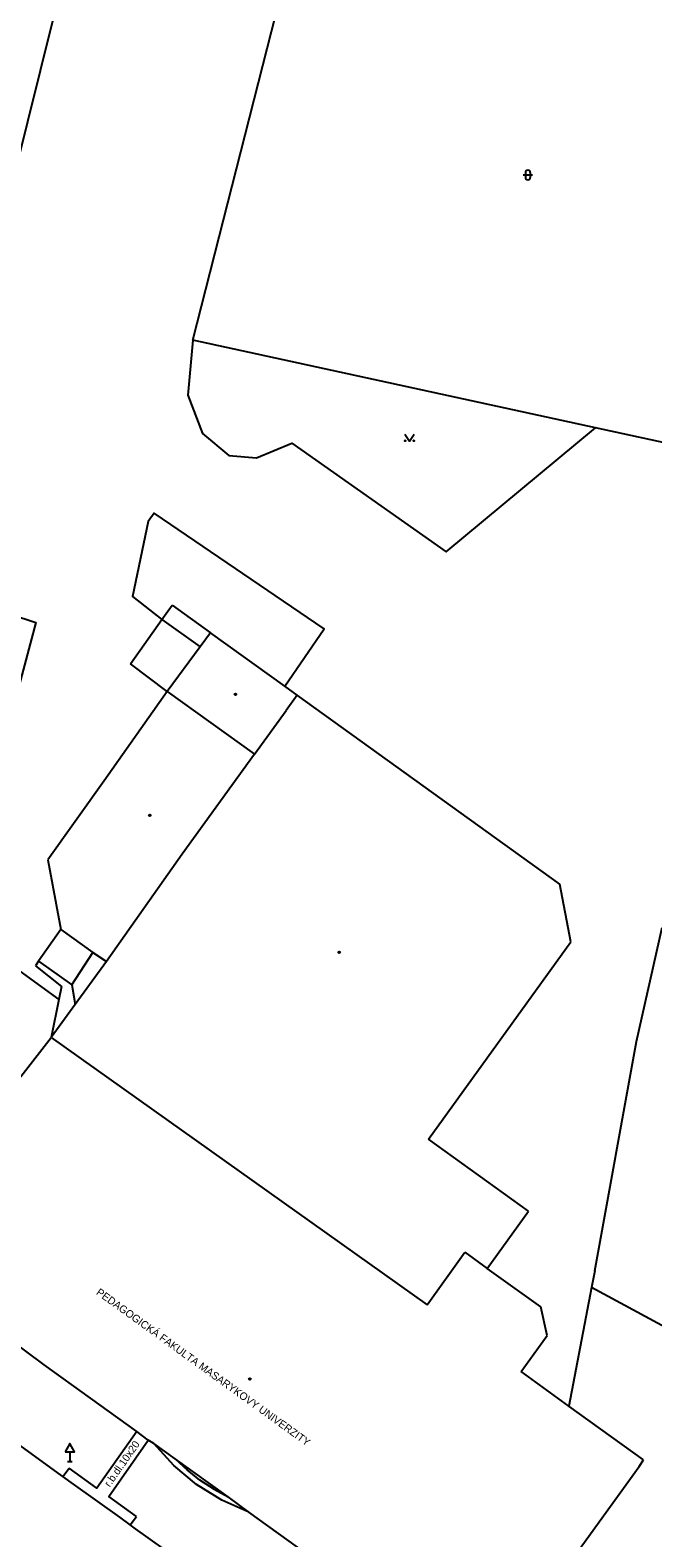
# Model space of a CAD drawing. Extents: x -599770 to -598493, y -1162076 to -1159209.
# Drawn here: x -599144.8 to -599111.9, y -1161563.7 to -1161484.3 of the extents above; entities that cross this region are included whole.
import ezdxf

# ---------------------------------------------------------------- set-up
doc = ezdxf.new("R2010")
doc.units = 0
doc.layers.add('Podklad', color=7, linetype='Continuous')

msp = doc.modelspace()

# ---------------------------------------------------------------- linework, layer by layer
at = {"layer": 'Podklad'}
for p, q in [((-599118.783, -1161491.928), (-599118.283, -1161491.928)), ((-599118.658, -1161491.803), (-599118.658, -1161492.053)), ((-599118.408, -1161491.803), (-599118.408, -1161492.053)), ((-599142.66, -1161559.191), (-599142.66, -1161559.7)), ((-599142.785, -1161559.7), (-599142.535, -1161559.7))]:
    msp.add_line(p, q, dxfattribs=at)
for points in [[(-599105.82, -1161507.23), (-599114.97, -1161505.24), (-599136.19, -1161500.63), (-599129.73, -1161475.32), (-599128.87, -1161471.95)], [(-599144.86, -1161473.56), (-599141.55, -1161475.68), (-599150.94, -1161513.38), (-599144.46, -1161515.5), (-599145.65, -1161520), (-599147.9, -1161521.32), (-599149.89, -1161521.98), (-599153.32, -1161522.38), (-599155.57, -1161521.59), (-599177.4, -1161507.96), (-599169.99, -1161493.94), (-599167.88, -1161494.47), (-599163.38, -1161497.91), (-599150.81, -1161486), (-599156.9, -1161476.47), (-599155.18, -1161473.43), (-599147.24, -1161478.06), (-599144.86, -1161473.56)], [(-599136.19, -1161500.63), (-599136.44, -1161503.52), (-599135.67, -1161505.55), (-599134.28, -1161506.7), (-599132.82, -1161506.82), (-599130.97, -1161506.06), (-599122.84, -1161511.78), (-599114.97, -1161505.24)], [(-599125.02, -1161505.575), (-599124.77, -1161505.95), (-599124.52, -1161505.575)], [(-599131.34, -1161518.86), (-599129.26, -1161515.84), (-599138.22, -1161509.75), (-599138.53, -1161510.19), (-599139.36, -1161514.13), (-599137.81, -1161515.35)], [(-599137.81, -1161515.35), (-599137.27, -1161514.59)], [(-599137.27, -1161514.59), (-599135.25, -1161516.04)], [(-599139.47, -1161517.68), (-599137.81, -1161515.35)], [(-599137.81, -1161515.35), (-599135.8, -1161516.79)], [(-599135.25, -1161516.04), (-599135.8, -1161516.79)], [(-599130.68, -1161519.33), (-599131.34, -1161518.86), (-599135.25, -1161516.04)], [(-599135.8, -1161516.79), (-599137.53, -1161519.14)], [(-599137.75, -1161564.29), (-599139.21, -1161563.25), (-599139.49, -1161563.04), (-599140.03, -1161562.64), (-599142.47, -1161560.9), (-599143.03, -1161560.49), (-599143.28, -1161560.31), (-599146.46, -1161558.01), (-599154.39, -1161552.27), (-599161.77, -1161546.92), (-599176.95, -1161535.88), (-599186.7, -1161528.83), (-599194.65, -1161523.08), (-599195.05, -1161522.79), (-599195.41, -1161522.53), (-599195.87, -1161522.2), (-599198.3, -1161520.43), (-599198.78, -1161520.08), (-599199.1, -1161519.85), (-599201.77, -1161517.89)], [(-599137.53, -1161519.14), (-599139.47, -1161517.68)], [(-599137.53, -1161519.14), (-599140.86, -1161523.85)], [(-599137.53, -1161519.14), (-599132.94, -1161522.44)], [(-599130.68, -1161519.33), (-599131.27, -1161520.14)], [(-599116.84, -1161529.29), (-599130.68, -1161519.33)], [(-599132.94, -1161522.44), (-599131.27, -1161520.14)], [(-599132.94, -1161522.44), (-599136.75, -1161527.7)], [(-599160.04, -1161523.17), (-599143.25, -1161535.36)], [(-599140.86, -1161523.85), (-599143.83, -1161528)], [(-599136.75, -1161527.7), (-599140.73, -1161533.36)], [(-599143.83, -1161528), (-599143.13, -1161531.67)], [(-599116.27, -1161532.33), (-599116.84, -1161529.29)], [(-599143.13, -1161531.67), (-599144.31, -1161533.35)], [(-599143.13, -1161531.67), (-599141.45, -1161532.88)], [(-599112.81, -1161537.58), (-599111.45, -1161531.57)], [(-599123.76, -1161542.73), (-599116.27, -1161532.33)], [(-599144.31, -1161533.35), (-599144.47, -1161533.59)], [(-599144.31, -1161533.35), (-599142.56, -1161534.6)], [(-599142.56, -1161534.6), (-599141.45, -1161532.88)], [(-599140.73, -1161533.36), (-599142.38, -1161535.62)], [(-599141.45, -1161532.88), (-599140.73, -1161533.36)], [(-599144.47, -1161533.59), (-599143.11, -1161534.68)], [(-599143.11, -1161534.68), (-599143.25, -1161535.36)], [(-599142.56, -1161534.6), (-599142.38, -1161535.62)], [(-599143.25, -1161535.36), (-599143.65, -1161537.36)], [(-599142.38, -1161535.62), (-599143.65, -1161537.36)], [(-599145.73, -1161540.05), (-599143.65, -1161537.36)], [(-599143.65, -1161537.36), (-599123.84, -1161551.45)], [(-599115.01, -1161549.65), (-599112.81, -1161537.58)], [(-599118.5, -1161546.52), (-599123.76, -1161542.73)], [(-599120.67, -1161549.53), (-599118.5, -1161546.52)], [(-599123.84, -1161551.45), (-599121.85, -1161548.68)], [(-599121.85, -1161548.68), (-599120.67, -1161549.53)], [(-599138.23, -1161558.76), (-599138.53, -1161558.58), (-599139.13, -1161558.13), (-599144.01, -1161554.61), (-599150.72, -1161549.63)], [(-599117.84, -1161551.56), (-599120.67, -1161549.53)], [(-599115.01, -1161549.65), (-599115.18, -1161550.54), (-599116.37, -1161556.78)], [(-599062.19, -1161579.16), (-599115.18, -1161550.54)], [(-599117.51, -1161553.07), (-599117.84, -1161551.56)], [(-599118.89, -1161554.97), (-599117.51, -1161553.07)], [(-599116.37, -1161556.78), (-599118.89, -1161554.97)], [(-599112.44, -1161559.62), (-599116.37, -1161556.78)], [(-599139.13, -1161558.13), (-599141.24, -1161561.1), (-599142.7, -1161560.05)], [(-599139.16, -1161562.6), (-599140.61, -1161561.55), (-599138.53, -1161558.58)], [(-599133.23, -1161562.37), (-599134.66, -1161561.74), (-599135.99, -1161560.92), (-599137.18, -1161559.92), (-599138.23, -1161558.76)], [(-599133.23, -1161562.37), (-599134.33, -1161561.57), (-599137.11, -1161559.57), (-599138.23, -1161558.76)], [(-599137.11, -1161559.57), (-599136.49, -1161560.15)], [(-599112.67, -1161559.96), (-599112.44, -1161559.62)], [(-599143.03, -1161560.49), (-599142.7, -1161560.05)], [(-599135.09, -1161561.15), (-599135.81, -1161560.68), (-599136.49, -1161560.15)], [(-599117.43, -1161566.55), (-599112.67, -1161559.96)], [(-599135.09, -1161561.15), (-599134.33, -1161561.57)], [(-599139.49, -1161563.04), (-599139.16, -1161562.6)], [(-599120.79, -1161571.31), (-599127.55, -1161566.47), (-599133.23, -1161562.37)]]:
    msp.add_lwpolyline(points, dxfattribs=at)
msp.add_lwpolyline([(-599142.91, -1161559.191), (-599142.41, -1161559.191), (-599142.66, -1161558.758)], close=True, dxfattribs=at)
for centre, radius in [((-599124.995, -1161505.925), 0.025), ((-599124.545, -1161505.925), 0.025), ((-599133.94, -1161519.29), 0.045), ((-599133.94, -1161519.29), 0.0199), ((-599138.45, -1161525.66), 0.045), ((-599138.45, -1161525.66), 0.0199), ((-599128.47, -1161532.88), 0.045), ((-599128.47, -1161532.88), 0.0199), ((-599133.18, -1161555.36), 0.045), ((-599133.18, -1161555.36), 0.0199)]:
    msp.add_circle(centre, radius, dxfattribs=at)
for centre, start, end in [((-599118.533, -1161491.803), 0, 180), ((-599118.533, -1161492.053), 180, 0)]:
    msp.add_arc(centre, 0.125, start, end, dxfattribs=at)

# ---------------------------------------------------------------- texts
for s, rotation, p in [('PEDAGOGICKÁ FAKULTA MASARYKOVY UNIVERZITY', 324.13797, (-599141.31, -1161550.87)), ('r.b.dl.10x20', 55, (-599140.56, -1161561.08))]:
    msp.add_text(s, height=0.4, rotation=rotation, dxfattribs=at).set_placement(p)

doc.saveas('drawing.dxf')
